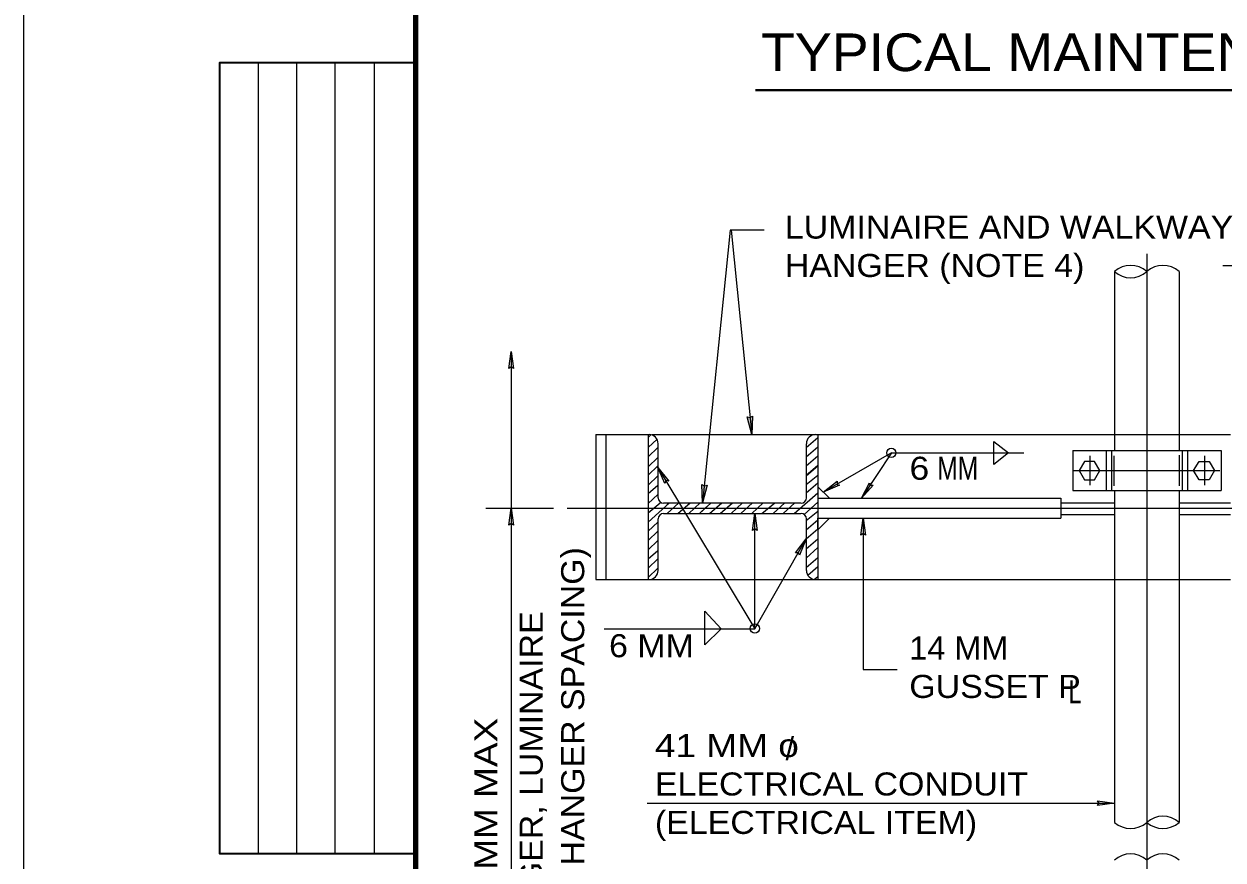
# Model space of a CAD drawing. Extents: x 312601.858 to 312602.699, y 144420.109 to 144420.704.
# Drawn here: x 312601.8578 to 312602.0138, y 144420.3467 to 144420.4555 of the extents above; entities that cross this region are included whole.
import ezdxf
from ezdxf.enums import TextEntityAlignment as Align

# ---------------------------------------------------------------- set-up
doc = ezdxf.new("R2010")
doc.units = 0
doc.header["$LTSCALE"] = 0.0012
for name, pattern in [('DOT_DASHED', [7.7, 5, -1.2, 0.3, -1.2]), ('LONG_DASHED', [7.5, 6, -1.5]), ('MEDIUM_DASHED', [4.5, 3, -1.5])]:
    doc.linetypes.add(name, pattern=pattern)
for name, color, linetype, lineweight in [('1', 7, 'Continuous', 13), ('2', 7, 'Continuous', 13), ('39', 7, 'Continuous', 13), ('60', 7, 'Continuous', 25)]:
    doc.layers.add(name, color=color, linetype=linetype, lineweight=lineweight)

msp = doc.modelspace()

# ---------------------------------------------------------------- hatches: boundary and pattern name
at = {"layer": '39'}
for points in [[(312601.9523, 144420.4043), (312601.9526, 144420.4045), (312601.9525, 144420.4021), (312601.9519, 144420.4044)], [(312601.9463, 144420.3954), (312601.9467, 144420.3955), (312601.9461, 144420.3932), (312601.946, 144420.3956)], [(312601.9463, 144420.3954), (312601.9467, 144420.3955), (312601.9461, 144420.3932), (312601.946, 144420.3956)]]:
    msp.add_hatch(color=256, dxfattribs=at).paths.add_polyline_path(points)

# ---------------------------------------------------------------- linework, layer by layer
at = {"layer": '1'}
for p, q in [((312601.9498, 144420.4287), (312601.9525, 144420.4021)), ((312602.0138, 144420.4241), (312602.0301, 144420.4241)), ((312601.939, 144420.4017), (312601.9394, 144420.4021)), ((312601.939, 144420.4004), (312601.9402, 144420.4015)), ((312601.9596, 144420.4004), (312601.9611, 144420.4017)), ((312601.939, 144420.3992), (312601.9403, 144420.4004)), ((312601.939, 144420.3979), (312601.9403, 144420.3991)), ((312601.9596, 144420.3992), (312601.9611, 144420.4005)), ((312601.9596, 144420.398), (312601.9611, 144420.3993)), ((312601.9707, 144420.3997), (312601.9668, 144420.3938)), ((312601.9707, 144420.3997), (312601.9879, 144420.3997)), ((312601.939, 144420.3968), (312601.9403, 144420.398)), ((312601.9403, 144420.3978), (312601.9529, 144420.3768)), ((312601.9596, 144420.3968), (312601.9611, 144420.3981)), ((312601.939, 144420.3955), (312601.9403, 144420.3967)), ((312601.9596, 144420.3956), (312601.9611, 144420.3968)), ((312601.939, 144420.3944), (312601.9403, 144420.3955)), ((312601.939, 144420.3931), (312601.9403, 144420.3943)), ((312601.958, 144420.3918), (312601.9611, 144420.3945)), ((312601.9596, 144420.3945), (312601.9611, 144420.3958)), ((312601.939, 144420.3907), (312601.9418, 144420.3932)), ((312601.939, 144420.3919), (312601.9406, 144420.3932)), ((312601.9415, 144420.393), (312601.9417, 144420.3932)), ((312601.9415, 144420.3918), (312601.943, 144420.3932)), ((312601.9429, 144420.3918), (312601.9445, 144420.3932)), ((312601.9443, 144420.3918), (312601.9458, 144420.3932)), ((312601.9457, 144420.3918), (312601.9472, 144420.3932)), ((312601.947, 144420.3918), (312601.9486, 144420.3932)), ((312601.9484, 144420.3918), (312601.95, 144420.3932)), ((312601.9498, 144420.3918), (312601.9513, 144420.3932)), ((312601.9511, 144420.3918), (312601.9526, 144420.3932)), ((312601.9525, 144420.3918), (312601.954, 144420.3932)), ((312601.9538, 144420.3918), (312601.9555, 144420.3932)), ((312601.9553, 144420.3918), (312601.9568, 144420.3932)), ((312601.9566, 144420.3918), (312601.9581, 144420.3932)), ((312601.9593, 144420.3917), (312601.9611, 144420.3933)), ((312601.9179, 144420.3925), (312601.9267, 144420.3925)), ((312601.9457, 144420.3918), (312601.9466, 144420.3927)), ((312601.9529, 144420.3768), (312601.9529, 144420.3918)), ((312601.9596, 144420.3909), (312601.9611, 144420.3921)), ((312601.9623, 144420.3925), (312601.993, 144420.3925)), ((312601.939, 144420.3895), (312601.9403, 144420.3907)), ((312601.9596, 144420.3897), (312601.9611, 144420.391)), ((312601.9596, 144420.3885), (312601.9611, 144420.3898)), ((312601.939, 144420.3883), (312601.9403, 144420.3895)), ((312601.939, 144420.3871), (312601.9403, 144420.3883)), ((312601.9529, 144420.3768), (312601.9596, 144420.3885)), ((312601.9596, 144420.3872), (312601.9611, 144420.3885)), ((312601.939, 144420.3859), (312601.9403, 144420.387)), ((312601.9596, 144420.386), (312601.9611, 144420.3874)), ((312601.939, 144420.3847), (312601.9403, 144420.3859)), ((312601.9596, 144420.3848), (312601.9611, 144420.3861)), ((312601.939, 144420.3835), (312601.9403, 144420.3847)), ((312601.9598, 144420.3838), (312601.9611, 144420.3849)), ((312601.9606, 144420.3832), (312601.9611, 144420.3836)), ((312601.9322, 144420.3832), (312601.9391, 144420.3832)), ((312601.9333, 144420.3768), (312601.9529, 144420.3768)), ((312601.9389, 144420.3541), (312601.9997, 144420.3541))]:
    msp.add_line(p, q, dxfattribs=at)
at = {"layer": '1', "linetype": 'DOT_DASHED'}
for p, q in [((312602.0039, 144420.4256), (312602.0039, 144420.2754)), ((312601.9965, 144420.3993), (312601.9965, 144420.3955)), ((312602.0114, 144420.3993), (312602.0114, 144420.3955)), ((312601.9944, 144420.3974), (312602.0134, 144420.3974)), ((312601.9285, 144420.3925), (312602.0203, 144420.3925))]:
    msp.add_line(p, q, dxfattribs=at)
at = {"layer": '1', "lineweight": 25}
for p, q in [((312601.9997, 144420.4233), (312601.9997, 144420.4)), ((312602.0081, 144420.4233), (312602.0081, 144420.4)), ((312601.9322, 144420.4021), (312601.9391, 144420.4021)), ((312601.9322, 144420.4021), (312601.9322, 144420.3832)), ((312601.9335, 144420.4021), (312601.9335, 144420.3832)), ((312601.939, 144420.4021), (312601.939, 144420.3832)), ((312601.9395, 144420.4021), (312601.9607, 144420.4021)), ((312601.9608, 144420.4021), (312601.9997, 144420.4021)), ((312601.9611, 144420.4021), (312601.9611, 144420.3953)), ((312602.0081, 144420.4021), (312602.0148, 144420.4021)), ((312601.9403, 144420.4009), (312601.9403, 144420.3938)), ((312601.9596, 144420.4009), (312601.9596, 144420.3938)), ((312601.9943, 144420.4), (312602.0136, 144420.4)), ((312601.9986, 144420.4), (312601.9986, 144420.3948)), ((312601.9993, 144420.4), (312601.9993, 144420.3948)), ((312602.0085, 144420.4), (312602.0085, 144420.3948)), ((312602.0092, 144420.4), (312602.0092, 144420.3948)), ((312602.0136, 144420.4), (312602.0136, 144420.3948)), ((312601.9596, 144420.3967), (312601.9611, 144420.398)), ((312601.9997, 144420.3948), (312601.9997, 144420.3516)), ((312602.0081, 144420.3948), (312602.0081, 144420.3516)), ((312601.941, 144420.3932), (312601.9589, 144420.3932)), ((312601.9611, 144420.3938), (312601.9611, 144420.3832)), ((312601.9626, 144420.3938), (312601.9927, 144420.3938)), ((312601.9927, 144420.3938), (312601.9927, 144420.3912)), ((312601.941, 144420.3918), (312601.9589, 144420.3918)), ((312601.9611, 144420.3912), (312601.9927, 144420.3912)), ((312601.9403, 144420.3911), (312601.9403, 144420.3844)), ((312601.9596, 144420.3911), (312601.9596, 144420.3844)), ((312601.9322, 144420.3832), (312601.9607, 144420.3832)), ((312601.9608, 144420.3832), (312601.9997, 144420.3832)), ((312602.0081, 144420.3832), (312602.0148, 144420.3832))]:
    msp.add_line(p, q, dxfattribs=at)
at = {"layer": '1', "linetype": 'LONG_DASHED', "lineweight": 25}
for p, q in [((312601.9997, 144420.4021), (312602.0081, 144420.4021)), ((312601.9997, 144420.3832), (312602.0081, 144420.3832))]:
    msp.add_line(p, q, dxfattribs=at)
at = {"layer": '1', "linetype": 'MEDIUM_DASHED', "lineweight": 25}
for p, q in [((312601.9996, 144420.3993), (312601.9996, 144420.3954)), ((312602.0081, 144420.3994), (312602.0081, 144420.3954))]:
    msp.add_line(p, q, dxfattribs=at)
at = {"layer": '1', "linetype": 'LONG_DASHED'}
for p, q in [((312601.9927, 144420.3932), (312601.9997, 144420.3932)), ((312602.0081, 144420.3932), (312602.0148, 144420.3932)), ((312601.9927, 144420.3917), (312601.9997, 144420.3917)), ((312602.0081, 144420.3917), (312602.0148, 144420.3917))]:
    msp.add_line(p, q, dxfattribs=at)
at = {"layer": '1'}
for points in [[(312601.9541, 144420.4287), (312601.9497, 144420.4287), (312601.9461, 144420.3932)], [(312601.9212, 144420.4129), (312601.9212, 144420.3925), (312601.9212, 144420.3062)], [(312601.967, 144420.3912), (312601.967, 144420.3715), (312601.9714, 144420.3715)]]:
    msp.add_lwpolyline(points, dxfattribs=at)
for points in [[(312601.9209, 144420.4107), (312601.9212, 144420.4129), (312601.9215, 144420.4107), (312601.9212, 144420.4109)], [(312601.9412, 144420.3957), (312601.9403, 144420.3978), (312601.9417, 144420.396), (312601.9413, 144420.3961)], [(312601.9639, 144420.3955), (312601.9618, 144420.3946), (312601.9636, 144420.396), (312601.9636, 144420.3956)], [(312601.9683, 144420.3955), (312601.9668, 144420.3938), (312601.9678, 144420.3958), (312601.9679, 144420.3955)], [(312601.9209, 144420.3903), (312601.9212, 144420.3925), (312601.9215, 144420.3903), (312601.9212, 144420.3905)], [(312601.9526, 144420.3896), (312601.9529, 144420.3918), (312601.9532, 144420.3896), (312601.9529, 144420.3898)], [(312601.9667, 144420.389), (312601.967, 144420.3912), (312601.9673, 144420.389), (312601.967, 144420.3892)], [(312601.9582, 144420.3867), (312601.9596, 144420.3885), (312601.9587, 144420.3864), (312601.9586, 144420.3867)], [(312601.9975, 144420.3544), (312601.9997, 144420.3541), (312601.9975, 144420.3538), (312601.9977, 144420.3541)]]:
    msp.add_lwpolyline(points, close=True, dxfattribs=at)
at = {"layer": '1', "lineweight": 25}
msp.add_lwpolyline([(312601.9943, 144420.4), (312601.9943, 144420.3948), (312602.0136, 144420.3948)], dxfattribs=at)
for points in [[(312601.9958, 144420.3962), (312601.9971, 144420.3962), (312601.9978, 144420.3974), (312601.9971, 144420.3986), (312601.9958, 144420.3986), (312601.9951, 144420.3974)], [(312602.012, 144420.3962), (312602.0107, 144420.3962), (312602.01, 144420.3974), (312602.0107, 144420.3986), (312602.012, 144420.3986), (312602.0127, 144420.3974)]]:
    msp.add_lwpolyline(points, close=True, dxfattribs=at)
at = {"layer": '1'}
for centre in [(312601.970665, 144420.399705), (312601.9529, 144420.37684)]:
    msp.add_circle(centre, 0.000595, dxfattribs=at)
for centre, radius, start, end in [((312602.0018, 144420.420944), 0.003156, 48.29108, 131.70892), ((312602.0018, 144420.420944), 0.003156, 48.29108, 131.70892), ((312602.0018, 144420.420944), 0.003156, 48.29108, 131.70892), ((312602.006, 144420.420944), 0.003156, 48.29108, 131.70892), ((312602.006, 144420.420944), 0.003156, 48.29108, 131.70892), ((312602.006, 144420.420944), 0.003156, 48.29108, 131.70892), ((312602.0018, 144420.425656), 0.003156, 228.29108, 311.70892), ((312602.0018, 144420.425656), 0.003156, 228.29108, 311.70892), ((312602.0018, 144420.425656), 0.003156, 228.29108, 311.70892), ((312601.958935, 144420.39384), 0.00068, 359.62724, 0), ((312602.006, 144420.349244), 0.003156, 48.29108, 131.70892), ((312602.006, 144420.349244), 0.003156, 48.29108, 131.70892), ((312602.006, 144420.349244), 0.003156, 48.29108, 131.70892), ((312602.0018, 144420.353956), 0.003156, 228.29108, 311.70892), ((312602.0018, 144420.353956), 0.003156, 228.29108, 311.70892), ((312602.0018, 144420.353956), 0.003156, 228.29108, 311.70892), ((312602.006, 144420.353956), 0.003156, 228.29108, 311.70892), ((312602.006, 144420.353956), 0.003156, 228.29108, 311.70892), ((312602.006, 144420.353956), 0.003156, 228.29108, 311.70892), ((312602.0018, 144420.344344), 0.003156, 48.29108, 131.70892), ((312602.0018, 144420.344344), 0.003156, 48.29108, 131.70892), ((312602.0018, 144420.344344), 0.003156, 48.29108, 131.70892), ((312602.006, 144420.344344), 0.003156, 48.29108, 131.70892), ((312602.006, 144420.344344), 0.003156, 48.29108, 131.70892), ((312602.006, 144420.344344), 0.003156, 48.29108, 131.70892)]:
    msp.add_arc(centre, radius, start, end, dxfattribs=at)
at = {"layer": '1', "lineweight": 25}
for centre, radius, start, end in [((312601.93913, 144420.400895), 0.00119, 0, 90), ((312601.960805, 144420.400895), 0.00119, 90, 180), ((312601.941, 144420.39384), 0.00068, 180, 270), ((312601.958935, 144420.39384), 0.00068, 270, 0), ((312601.941, 144420.39112), 0.00068, 90, 180), ((312601.958935, 144420.39112), 0.00068, 0, 90), ((312601.93913, 144420.384405), 0.00119, 270, 0), ((312601.960805, 144420.384405), 0.00119, 180, 270)]:
    msp.add_arc(centre, radius, start, end, dxfattribs=at)
at = {"layer": '2', "lineweight": 40}
msp.add_line((312601.953, 144420.4469), (312602.1068, 144420.4469), dxfattribs=at)
at = {"layer": '2'}
msp.add_line((312601.9707, 144420.3997), (312601.9618, 144420.3946), dxfattribs=at)
for points in [[(312601.984, 144420.3982), (312601.984, 144420.4012), (312601.9859, 144420.3997)], [(312601.9611, 144420.3938), (312601.9626, 144420.3938), (312601.9611, 144420.3953)], [(312601.9611, 144420.3912), (312601.9626, 144420.3912), (312601.9611, 144420.3897)], [(312601.9464, 144420.3747), (312601.9464, 144420.3791), (312601.9485, 144420.3768)]]:
    msp.add_lwpolyline(points, close=True, dxfattribs=at)
at = {"layer": '39', "lineweight": 25}
msp.add_line((312601.8578, 144420.1095), (312601.8578, 144420.7035), dxfattribs=at)
at = {"layer": '39', "lineweight": 158}
msp.add_lwpolyline([(312601.9088, 144420.1247), (312601.9088, 144420.6645), (312602.6838, 144420.6645)], dxfattribs=at)
at = {"layer": '39'}
for points in [[(312601.9523, 144420.4043), (312601.9526, 144420.4045), (312601.9525, 144420.4021), (312601.9519, 144420.4044)], [(312601.9463, 144420.3954), (312601.9467, 144420.3955), (312601.9461, 144420.3932), (312601.946, 144420.3956)], [(312601.9463, 144420.3954), (312601.9467, 144420.3955), (312601.9461, 144420.3932), (312601.946, 144420.3956)]]:
    msp.add_lwpolyline(points, close=True, dxfattribs=at)
at = {"layer": '60'}
for p, q in [((312601.8883, 144420.3475), (312601.8883, 144420.4505)), ((312601.8933, 144420.3475), (312601.8933, 144420.4505)), ((312601.8983, 144420.3475), (312601.8983, 144420.4505)), ((312601.9034, 144420.3475), (312601.9034, 144420.4505))]:
    msp.add_line(p, q, dxfattribs=at)
at = {"layer": '60', "lineweight": 35}
msp.add_lwpolyline([(312601.9084, 144420.3475), (312601.8833, 144420.3475), (312601.8833, 144420.4505), (312601.9084, 144420.4505)], dxfattribs=at)

# ---------------------------------------------------------------- texts
at = {"layer": '2'}
for s, height, width, p in [('TYPICAL MAINTENANCE WALKWAY DETAIL', 0.0049, 1.1, (312601.9537, 144420.4494)), ('LUMINAIRE AND WALKWAY', 0.003, 1.1, (312601.9568, 144420.4276)), ('HANGER (NOTE 4)', 0.003, 1.1, (312601.9568, 144420.4226)), ('14 MM', 0.003, 1.05, (312601.973, 144420.3728)), ('GUSSET P', 0.003, 1.1, (312601.973, 144420.3678)), ('41 MM o', 0.003, 1.2, (312601.9399, 144420.3601)), ('ELECTRICAL CONDUIT', 0.003, 1.1, (312601.9399, 144420.3551)), ('(ELECTRICAL ITEM)', 0.003, 1.1, (312601.9399, 144420.3501))]:
    msp.add_text(s, height=height, dxfattribs=dict(at, width=width)).set_placement(p)
for s, width, p in [('6 ', 1.15, (312601.97495, 144420.3962)), ('MM', 0.8, (312601.9793, 144420.3962)), ('6 MM', 1.1, (312601.93945, 144420.3731)), ('L', 0.75, (312601.99455, 144420.3671))]:
    msp.add_text(s, height=0.003, dxfattribs=dict(at, width=width)).set_placement(p, align=Align.CENTER)
for s, width, p in [('AND WALKWAY HANGER SPACING)', 1.1, (312601.9307, 144420.34955)), ('(SIGN HANGER, LUMINAIRE', 1.1, (312601.9253, 144420.34965)), ('1500 MM MAX', 1.2, (312601.9194, 144420.3493))]:
    msp.add_text(s, height=0.003, rotation=90, dxfattribs=dict(at, width=width)).set_placement(p, align=Align.CENTER)
msp.add_text('/', height=0.003, dxfattribs=at).set_placement((312601.95745, 144420.3597), align=Align.CENTER)

doc.saveas('drawing.dxf')
